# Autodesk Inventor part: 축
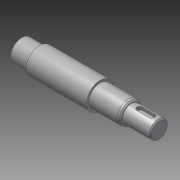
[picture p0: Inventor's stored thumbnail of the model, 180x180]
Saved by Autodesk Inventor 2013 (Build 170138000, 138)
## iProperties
Created: 2016-06
Part Number: 축
Material: 강철, 연강
Document SubType Name: Modeling
Designer: mduedu
Density: 7.86 g/cm^3
Author: mduedu
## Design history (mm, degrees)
sketch "스케치1"
  geometry: L1 (-62, 0)-(62, 0); L2 (-62, 0)-(-62, 10); L3 (-62, 10)-(-45, 10); L4 (-45, 10)-(-45, 12); L5 (-45, 12)-(9, 12); L6 (9, 12)-(9, 10); L7 (9, 10)-(37, 10); L8 (37, 10)-(37, 8); L9 (37, 8)-(62, 8); L10 (62, 8)-(62, 0); 2 further points
  constraints: 20 end point, 5 parallel, 2 perpendicular, 1 coincident, 1 collinear, 1 horizontal, 1 midpoint, 1 vertical
  dimensions: "d0" = 124 distance of L1.start L1.end; "d2" = 16 diameter of L9 L1; "d3" = 20 diameter of L7 L1; "d4" = 24 diameter of L5 L1; "d5" = 20 diameter of L3 L1; "d6" = 17 distance of L2.end L3.end; "d7" = 25 distance of L8.end L9.end; "d8" = 53 distance from line of L5.end L10
revolve "회전1" sketch "스케치1" stored, may be unused: angle "d9" = 90 deg
chamfer "모따기1" distance "d10" = 2; stored, may be unused: second distance "d11" = 2, angle "d12" = 30 deg
fillet "모깎기1" dims "d13" = 4
node "작업 평면1"
sketch "스케치2"
  geometry: L1 (-5, 2.5)-(6, 2.5); L2 (6, -2.5)-(-5, -2.5); L3 (-5, 0)-(6, 0); L4 (-12.5, 8.845)-(-12.5, -8.845) reference; A1 r 2.5 centre (-5, 0) between (-5, 2.5) and (-5, -2.5); A2 r 2.5 centre (6, 0) between (6, -2.5) and (6, 2.5); 1 further point
  constraints: 6 end point, 4 point on circle, 3 tangent, 2 centre point, 2 parallel, 1 horizontal, 1 horizontal alignment
  dimensions: "d14" = 5 distance edge to line of A1 L4; "d15" = 5 distance between parallel lines of L2 L1; "d16" = 16 dimension on A2 A1
extrude "돌출1" cut sketch "스케치2" distance "d17" = 3; taper "d18" = 0 deg
chamfer "모따기2" distance "d19" = 1; stored, may be unused: second distance "d20" = 2, angle "d21" = 30 deg
sketch "스케치3"
  geometry: L1 (-37, -8)-(-61, -8) reference; L2 (-62, -7)-(-62, 7) reference; L3 (-38.5, -8)-(-40, -6.5); L4 (-40, -6.5)-(-40, -8); L5 (-38.5, -8)-(-40, -8); 1 further point
  constraints: 6 end point, 2 point on line, 1 collinear, 1 vertical
  dimensions: "d22" = 45 deg angle of L4 L3; "d23" = 22 distance between parallel lines of L2 L4; "d24" = 3 diameter of L3.start L4
revolve "회전2" stored, may be unused: angle "d25" = 90 deg
node "작업점1"
sketch "스케치4"
  geometry: 1 further point
hole "구멍1" sketch "스케치4" at (0, 0) diameter "d26" = 3.242; stored, may be unused: countersink angle "d30" = 90 deg, drill point angle "d32" = 120 deg; dims "d27" = 8, "d28" = 4, "d29" = 2, "d31" = 11
chamfer "모따기3" distance "d33" = 2; stored, may be unused: second distance "d34" = 2, angle "d35" = 30 deg
node "솔리드1"
pattern_circular "원형 패턴1" dims angle "d37" = 90 deg
node "작업점2"
